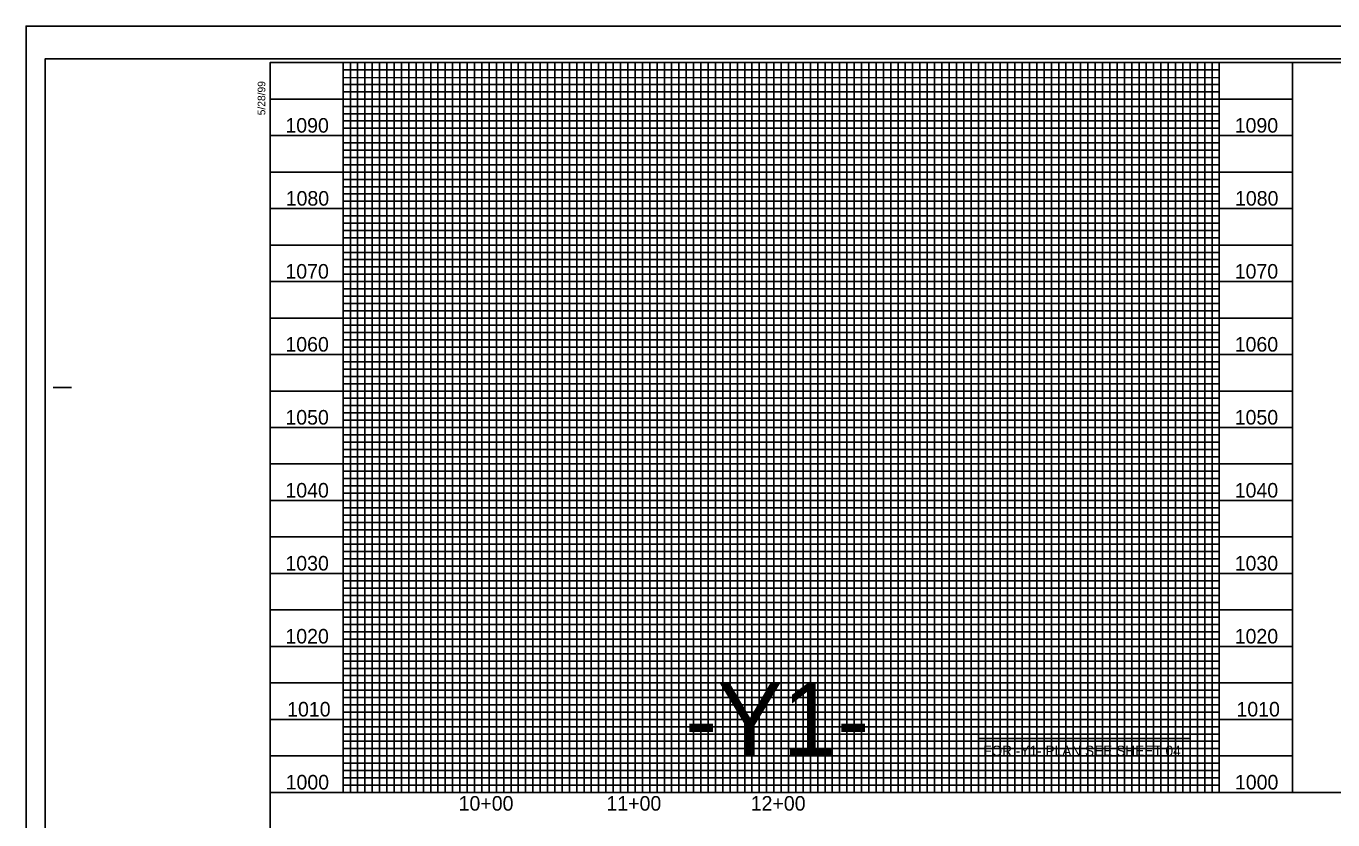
# Model space of a CAD drawing. Extents: x 1260439 to 1262228, y 742196 to 743296.
# Drawn here: x 1260439 to 1261333, y 742752 to 743296 of the extents above; entities that cross this region are included whole.
import ezdxf

# ---------------------------------------------------------------- set-up
doc = ezdxf.new("R2010")
doc.units = 0
for name, color, linetype in [('Exist Vertical Profile Horizontal Axis Label Major', 7, 'Continuous'), ('Exist Vertical Profile Vertical Axis Label', 7, 'Continuous'), ('Prop Grid Mask', 7, 'Continuous'), ('Prop PFL Text', 7, 'Continuous'), ('Scratch_Level_0', 7, 'Continuous'), ('Sheet Cutting Line CELL', 7, 'Continuous'), ('Sheet Data Field CELL', 7, 'Continuous'), ('Sheet Layout Profile Border Port 1', 7, 'Continuous'), ('Sheet Plot Border Inside CELL', 7, 'Continuous'), ('Sheet Plot Border Outside CELL', 7, 'Continuous'), ('Sheet Profile CELL', 7, 'Continuous'), ('Sheet Profile Grid Major CELL', 7, 'Continuous'), ('Sheet Profile Grid Middle CELL', 7, 'Continuous'), ('Sheet Profile Grid Minor CELL', 7, 'Continuous')]:
    doc.layers.add(name, color=color, linetype=linetype)

msp = doc.modelspace()

# ---------------------------------------------------------------- linework, layer by layer
at = {"layer": 'Prop Grid Mask'}
msp.add_lwpolyline([(1261090.75, 742807.74), (1261235.75, 742807.74), (1261235.75, 742790.74), (1261090.75, 742790.74)], close=True, dxfattribs=at)
at = {"layer": 'Scratch_Level_0'}
msp.add_lwpolyline([(1260755.75, 743270.74), (1261355.75, 743270.74), (1261355.75, 742770.74), (1260755.75, 742770.74)], close=True, dxfattribs=at)
at = {"layer": 'Sheet Cutting Line CELL'}
for p, q in [((1262122.75, 743295.74), (1260438.75, 743295.74)), ((1260438.75, 743295.74), (1260438.75, 742195.74))]:
    msp.add_line(p, q, dxfattribs=at)
at = {"layer": 'Sheet Layout Profile Border Port 1'}
msp.add_lwpolyline([(1260655.75, 742770.74), (1261305.75, 742770.74), (1261305.75, 743270.74), (1260655.75, 743270.74)], close=True, dxfattribs=at)
msp.add_lwpolyline([(1260655.75, 743109.69), (1260655.75, 742770.74), (1262055.75, 742770.74), (1262055.75, 743109.69)], dxfattribs=at)
msp.add_lwpolyline([(1260655.75, 743109.69), (1260655.75, 742770.74), (1262055.75, 742770.74), (1262055.75, 743109.69)], dxfattribs=at)
msp.add_lwpolyline([(1260655.75, 743109.69), (1260655.75, 742770.74), (1262055.75, 742770.74), (1262055.75, 743109.69)], dxfattribs=at)
at = {"layer": 'Sheet Plot Border Inside CELL'}
msp.add_lwpolyline([(1260451.75, 742218.19), (1262118.25, 742218.19), (1262118.25, 743273.29), (1260451.75, 743273.29)], close=True, dxfattribs=at)
at = {"layer": 'Sheet Plot Border Outside CELL'}
msp.add_lwpolyline([(1260438.75, 742195.74), (1262122.75, 742195.74), (1262122.75, 743295.74), (1260438.75, 743295.74)], close=True, dxfattribs=at)
at = {"layer": 'Sheet Profile CELL'}
for p, q in [((1260457.25, 743048.24), (1260469.75, 743048.24)), ((1260605.75, 742770.74), (1262105.75, 742770.74))]:
    msp.add_line(p, q, dxfattribs=at)
msp.add_lwpolyline([(1262105.75, 743270.74), (1260605.75, 743270.74), (1260605.75, 742220.74), (1262105.75, 742220.74)], close=True, dxfattribs=at)
at = {"layer": 'Sheet Profile Grid Major CELL'}
for p, q in [((1260655.75, 743270.74), (1260655.75, 742770.74)), ((1260705.75, 742770.74), (1260705.75, 743270.74)), ((1260705.75, 743270.74), (1260755.75, 743270.74)), ((1260755.75, 743270.74), (1260755.75, 742770.74)), ((1260805.75, 742770.74), (1260805.75, 743270.74)), ((1260805.75, 743270.74), (1260855.75, 743270.74)), ((1260855.75, 743270.74), (1260855.75, 742770.74)), ((1260905.75, 742770.74), (1260905.75, 743270.74)), ((1260905.75, 743270.74), (1260955.75, 743270.74)), ((1260955.75, 743270.74), (1260955.75, 742770.74)), ((1261005.75, 742770.74), (1261005.75, 743270.74)), ((1261005.75, 743270.74), (1261055.75, 743270.74)), ((1261055.75, 743270.74), (1261055.75, 742770.74)), ((1261105.75, 742770.74), (1261105.75, 743270.74)), ((1261105.75, 743270.74), (1261155.75, 743270.74)), ((1261155.75, 743270.74), (1261155.75, 742770.74)), ((1261205.75, 742770.74), (1261205.75, 743270.74)), ((1261255.75, 743270.74), (1261255.75, 742770.74)), ((1261305.75, 742770.74), (1261305.75, 743270.74)), ((1260655.75, 742770.74), (1260705.75, 742770.74)), ((1260755.75, 742770.74), (1260805.75, 742770.74)), ((1260855.75, 742770.74), (1260905.75, 742770.74)), ((1260955.75, 742770.74), (1261005.75, 742770.74)), ((1261055.75, 742770.74), (1261105.75, 742770.74)), ((1261155.75, 742770.74), (1261205.75, 742770.74)), ((1261255.75, 742770.74), (1261305.75, 742770.74))]:
    msp.add_line(p, q, dxfattribs=at)
for points in [[(1260605.75, 743220.74), (1261305.75, 743220.74)], [(1261305.75, 743170.74), (1260605.75, 743170.74), (1260605.75, 743120.74), (1261305.75, 743120.74)], [(1261305.75, 743070.74), (1260605.75, 743070.74), (1260605.75, 743020.74), (1261305.75, 743020.74)], [(1261305.75, 742970.74), (1260605.75, 742970.74), (1260605.75, 742920.74), (1261305.75, 742920.74)], [(1261305.75, 742870.74), (1260605.75, 742870.74), (1260605.75, 742870.74), (1260605.75, 742820.74), (1261305.75, 742820.74)]]:
    msp.add_lwpolyline(points, dxfattribs=at)
at = {"layer": 'Sheet Profile Grid Middle CELL'}
for p, q in [((1260680.75, 743270.74), (1260680.75, 742770.74)), ((1260730.75, 742770.74), (1260730.75, 743270.74)), ((1260730.75, 743270.74), (1260780.75, 743270.74)), ((1260780.75, 743270.74), (1260780.75, 742770.74)), ((1260830.75, 742770.74), (1260830.75, 743270.74)), ((1260830.75, 743270.74), (1260880.75, 743270.74)), ((1260880.75, 743270.74), (1260880.75, 742770.74)), ((1260930.75, 742770.74), (1260930.75, 743270.74)), ((1260930.75, 743270.74), (1260980.75, 743270.74)), ((1260980.75, 743270.74), (1260980.75, 742770.74)), ((1261030.75, 742770.74), (1261030.75, 743270.74)), ((1261030.75, 743270.74), (1261080.75, 743270.74)), ((1261080.75, 743270.74), (1261080.75, 742770.74)), ((1261130.75, 742770.74), (1261130.75, 743270.74)), ((1261180.75, 743270.74), (1261180.75, 742770.74)), ((1261230.75, 742770.74), (1261230.75, 743270.74)), ((1260605.75, 743245.74), (1261305.75, 743245.74)), ((1260680.75, 742770.74), (1260730.75, 742770.74)), ((1260780.75, 742770.74), (1260830.75, 742770.74)), ((1260880.75, 742770.74), (1260930.75, 742770.74)), ((1260980.75, 742770.74), (1261030.75, 742770.74)), ((1261080.75, 742770.74), (1261130.75, 742770.74)), ((1261230.75, 742770.74), (1261230.75, 742770.74))]:
    msp.add_line(p, q, dxfattribs=at)
for points in [[(1261305.75, 743195.74), (1260605.75, 743195.74), (1260605.75, 743145.74), (1261305.75, 743145.74)], [(1261305.75, 743095.74), (1260605.75, 743095.74), (1260605.75, 743045.74), (1261305.75, 743045.74)], [(1261305.75, 742995.74), (1260605.75, 742995.74), (1260605.75, 742945.74), (1261305.75, 742945.74)], [(1261305.75, 742895.74), (1260605.75, 742895.74), (1260605.75, 742845.74), (1261305.75, 742845.74)], [(1261305.75, 742795.74), (1260605.75, 742795.74)]]:
    msp.add_lwpolyline(points, dxfattribs=at)
at = {"layer": 'Sheet Profile Grid Minor CELL'}
for p, q in [((1260655.75, 743265.74), (1261255.75, 743265.74)), ((1260655.75, 743260.74), (1260655.75, 743260.74)), ((1261255.75, 743260.56), (1260655.75, 743260.39)), ((1260655.75, 743255.74), (1261255.75, 743255.74)), ((1261255.75, 743135.74), (1260655.75, 743135.74)), ((1261255.75, 743130.74), (1260655.75, 743130.74)), ((1261255.75, 743125.74), (1260655.75, 743125.74)), ((1260655.75, 743115.74), (1261255.75, 743115.74)), ((1261255.75, 743110.74), (1260655.75, 743110.74)), ((1260655.75, 743105.74), (1261255.75, 743105.74)), ((1261255.75, 743085.74), (1260655.75, 743085.74)), ((1260655.75, 743080.74), (1261255.75, 743080.74)), ((1261255.75, 743060.74), (1260655.75, 743060.74)), ((1260655.75, 743055.74), (1261255.75, 743055.74)), ((1261255.75, 743035.74), (1260655.75, 743035.74)), ((1260655.75, 743030.74), (1261255.75, 743030.74)), ((1261255.75, 743025.74), (1260655.75, 743025.74)), ((1260655.75, 743015.74), (1261255.75, 743015.74)), ((1261255.75, 743010.74), (1260655.75, 743010.74)), ((1260655.75, 743005.74), (1261255.75, 743005.74)), ((1261255.75, 743000.74), (1260655.75, 743000.74)), ((1260655.75, 742990.74), (1261255.75, 742990.74)), ((1261255.75, 742985.74), (1260655.75, 742985.74)), ((1260655.75, 742980.74), (1261255.75, 742980.74)), ((1261255.75, 742975.74), (1260655.75, 742975.74)), ((1260655.75, 742965.74), (1261255.75, 742965.74)), ((1261255.75, 742960.74), (1260655.75, 742960.74)), ((1260655.75, 742955.74), (1261255.75, 742955.74)), ((1261255.75, 742950.74), (1260655.75, 742950.74)), ((1260655.75, 742940.74), (1261255.75, 742940.74)), ((1261255.75, 742935.74), (1260655.75, 742935.74)), ((1260655.75, 742930.74), (1261255.75, 742930.74)), ((1261255.75, 742925.74), (1260655.75, 742925.74)), ((1260655.75, 742915.74), (1261255.75, 742915.74)), ((1261255.75, 742910.74), (1260655.75, 742910.74)), ((1260655.75, 742905.74), (1261255.75, 742905.74)), ((1261255.75, 742900.74), (1260655.75, 742900.74)), ((1260655.75, 742890.74), (1261255.75, 742890.74)), ((1261255.75, 742885.74), (1260655.75, 742885.74)), ((1261255.75, 742880.74), (1260655.75, 742880.74)), ((1261255.75, 742875.74), (1260655.75, 742875.74)), ((1260655.75, 742865.74), (1261255.75, 742865.74)), ((1261255.75, 742860.74), (1260655.75, 742860.74)), ((1260655.75, 742855.74), (1261255.75, 742855.74)), ((1261255.75, 742850.74), (1260655.75, 742850.74)), ((1260655.75, 742840.74), (1261255.75, 742840.74)), ((1261255.75, 742835.74), (1260655.75, 742835.74)), ((1260655.75, 742830.74), (1261255.75, 742830.74)), ((1261255.75, 742825.74), (1260655.75, 742825.74)), ((1260655.75, 742815.74), (1261255.75, 742815.74)), ((1261255.75, 742810.74), (1260655.75, 742810.74)), ((1260655.75, 742805.74), (1261255.75, 742805.74)), ((1261255.75, 742800.74), (1260655.75, 742800.74)), ((1260655.75, 742790.74), (1261255.75, 742790.74)), ((1261255.75, 742785.74), (1260655.75, 742785.74)), ((1260655.75, 742780.74), (1261255.75, 742780.74))]:
    msp.add_line(p, q, dxfattribs=at)
for points in [[(1260660.75, 743270.74), (1260660.75, 742770.74), (1260665.75, 742770.74), (1260665.75, 743270.74), (1260670.75, 743270.74), (1260670.75, 742770.74), (1260675.75, 742770.74), (1260675.75, 743270.74), (1260685.75, 743270.74), (1260685.75, 742770.74), (1260690.75, 742770.74), (1260690.75, 743270.74), (1260695.75, 743270.74), (1260695.75, 742770.74), (1260700.75, 742770.74), (1260710.75, 742770.74), (1260715.75, 742770.74), (1260715.75, 743270.74), (1260720.75, 743270.74), (1260720.75, 742770.74), (1260725.75, 742770.74), (1260725.75, 743270.74), (1260735.75, 743270.74), (1260735.75, 742770.74), (1260740.75, 742770.74), (1260740.75, 743270.74), (1260745.75, 743270.74), (1260745.75, 742770.74), (1260750.75, 742770.74), (1260750.75, 743270.74), (1260760.75, 743270.74), (1260760.75, 742770.74), (1260765.75, 742770.74), (1260765.75, 743270.74), (1260770.75, 743270.74), (1260770.75, 742770.74), (1260775.75, 742770.74), (1260775.75, 743270.74), (1260785.75, 743270.74), (1260785.75, 742770.74), (1260790.75, 742770.74), (1260790.75, 743270.74), (1260795.75, 743270.74), (1260795.75, 742770.74), (1260800.75, 742770.74), (1260800.75, 743270.74), (1260810.75, 743270.74), (1260810.75, 742770.74), (1260815.75, 742770.74), (1260815.75, 743270.74), (1260820.75, 743270.74), (1260820.75, 742770.74), (1260825.75, 742770.74), (1260825.75, 743270.74), (1260835.75, 743270.74), (1260835.75, 742770.74), (1260840.75, 742770.74), (1260840.75, 743270.74), (1260845.75, 743270.74), (1260845.75, 742770.74), (1260850.75, 742770.74), (1260850.75, 743270.74), (1260860.75, 743270.74), (1260860.75, 742770.74), (1260865.75, 742770.74), (1260865.75, 743270.74), (1260870.75, 743270.74), (1260870.75, 742770.74)], [(1260700.75, 742770.74), (1260700.75, 743270.74), (1260710.75, 743270.74), (1260710.75, 742770.74)], [(1260870.75, 742770.74), (1260875.75, 742770.74), (1260875.75, 743270.74), (1260885.75, 743270.74), (1260885.75, 742770.74), (1260890.75, 742770.74), (1260890.75, 743270.74), (1260895.75, 743270.74), (1260895.75, 742770.74), (1260900.75, 742770.74), (1260900.75, 743270.74), (1260910.75, 743270.74), (1260910.75, 742770.74), (1260915.75, 742770.74), (1260915.75, 743270.74), (1260920.75, 743270.74), (1260920.75, 742770.74), (1260925.75, 742770.74), (1260925.75, 743270.74), (1260935.75, 743270.74), (1260935.75, 742770.74), (1260940.75, 742770.74), (1260940.75, 743270.74), (1260945.75, 743270.74), (1260945.75, 742770.74), (1260950.75, 742770.74), (1260950.75, 743270.74), (1260960.75, 743270.74), (1260960.75, 742770.74), (1260965.75, 742770.74), (1260965.75, 743270.74), (1260970.75, 743270.74), (1260970.75, 742770.74), (1260975.75, 742770.74), (1260975.75, 743270.74), (1260985.75, 743270.74), (1260985.75, 742770.74), (1260990.75, 742770.74), (1260990.75, 743270.74), (1260995.75, 743270.74), (1260995.75, 742770.74), (1261000.75, 742770.74), (1261000.75, 743270.74), (1261010.75, 743270.74), (1261010.75, 742770.74), (1261015.75, 742770.74), (1261015.75, 743270.74), (1261020.75, 743270.74), (1261020.75, 742770.74), (1261025.75, 742770.74), (1261025.75, 743270.74), (1261035.75, 743270.74), (1261035.75, 742770.74), (1261040.75, 742770.74), (1261040.75, 743270.74), (1261045.75, 743270.74), (1261045.75, 742770.74), (1261050.75, 742770.74), (1261050.75, 743270.74), (1261060.75, 743270.74), (1261060.75, 742770.74), (1261065.75, 742770.74), (1261065.75, 743270.74), (1261070.75, 743270.74), (1261070.75, 742770.74), (1261075.75, 742770.74), (1261075.75, 743270.74), (1261085.75, 743270.74), (1261085.75, 742770.74), (1261090.75, 742770.74), (1261090.75, 743270.74), (1261095.75, 743270.74), (1261095.75, 742770.74), (1261100.75, 742770.74), (1261100.75, 743270.74), (1261110.75, 743270.74), (1261110.75, 742770.74), (1261115.75, 742770.74), (1261115.75, 743270.74), (1261120.75, 743270.74), (1261120.75, 742770.74), (1261125.75, 742770.74), (1261125.75, 743270.74), (1261135.75, 743270.74), (1261135.75, 742770.74), (1261140.75, 742770.74), (1261140.75, 743270.74), (1261145.75, 743270.74), (1261145.75, 742770.74), (1261150.75, 742770.74), (1261150.75, 743270.74), (1261255.75, 743270.74)], [(1261145.75, 742770.74), (1261150.75, 742770.74), (1261150.75, 743270.74), (1261160.75, 743270.74), (1261160.75, 742770.74), (1261165.75, 742770.74), (1261165.75, 743270.74), (1261170.75, 743270.74), (1261170.75, 742770.74), (1261175.75, 742770.74), (1261175.75, 743270.74), (1261185.75, 743270.74), (1261185.75, 742770.74), (1261190.75, 742770.74), (1261190.75, 743270.74), (1261195.75, 743270.74), (1261195.75, 742770.74), (1261200.75, 742770.74), (1261200.75, 743270.74), (1261210.75, 743270.74), (1261210.75, 742770.74), (1261215.75, 742770.74), (1261215.75, 743270.74), (1261220.75, 743270.74), (1261220.75, 742770.74), (1261225.75, 742770.74), (1261225.75, 743270.74), (1261235.75, 743270.74), (1261235.75, 742770.74), (1261240.75, 742770.74), (1261240.75, 743270.74), (1261245.75, 743270.74), (1261245.75, 742770.74), (1261250.75, 742770.74), (1261250.75, 743270.74), (1261255.75, 743270.74)], [(1261255.75, 743250.74), (1260655.75, 743250.74), (1260655.75, 743240.74), (1261255.75, 743240.74)], [(1261255.75, 743235.74), (1260655.75, 743235.74), (1260655.75, 743230.74), (1261255.75, 743230.74)], [(1261255.75, 743225.74), (1260655.75, 743225.74), (1260655.75, 743215.74), (1261255.75, 743215.74)], [(1261255.75, 743210.74), (1260655.75, 743210.74), (1260655.75, 743205.74), (1261255.75, 743205.74)], [(1261255.75, 743200.74), (1260655.75, 743200.74), (1260655.75, 743190.74), (1261255.75, 743190.74)], [(1261255.75, 743185.74), (1260655.75, 743185.74), (1260655.75, 743180.74), (1261255.75, 743180.74)], [(1261255.75, 743175.74), (1260655.75, 743175.74), (1260655.75, 743165.74), (1261255.75, 743165.74)], [(1261255.75, 743160.64), (1260655.85, 743160.64), (1260655.85, 743155.74), (1261255.75, 743155.74)], [(1261255.75, 743150.74), (1260655.75, 743150.74), (1260655.75, 743140.74), (1261255.75, 743140.74)], [(1261255.75, 743100.74), (1260655.75, 743100.74), (1260655.75, 743090.74), (1261255.75, 743090.74)], [(1261255.75, 743075.74), (1260655.75, 743075.74), (1260655.75, 743065.74), (1261255.75, 743065.74)], [(1261255.75, 743050.74), (1260655.75, 743050.74), (1260655.75, 743040.74), (1261255.75, 743040.74)], [(1261255.75, 742775.74), (1260655.75, 742775.74)]]:
    msp.add_lwpolyline(points, dxfattribs=at)

# ---------------------------------------------------------------- texts
at = {"layer": 'Exist Vertical Profile Horizontal Axis Label Major'}
for s, p in [('10+00', (1260734.88, 742758.24)), ('11+00', (1260836.08, 742758.24)), ('12+00', (1260934.88, 742758.24))]:
    msp.add_text(s, height=10, dxfattribs=at).set_placement(p)
at = {"layer": 'Exist Vertical Profile Vertical Axis Label'}
for s, p in [('1090', (1260616.27, 743222.74)), ('1090', (1261266.27, 743222.74)), ('1080', (1260616.47, 743172.74)), ('1080', (1261266.47, 743172.74)), ('1070', (1260616.27, 743122.74)), ('1070', (1261266.27, 743122.74)), ('1060', (1260616.27, 743072.74)), ('1060', (1261266.27, 743072.74)), ('1050', (1260616.27, 743022.74)), ('1050', (1261266.27, 743022.74)), ('1040', (1260616.27, 742972.74)), ('1040', (1261266.27, 742972.74)), ('1030', (1260616.27, 742922.74)), ('1030', (1261266.27, 742922.74)), ('1020', (1260616.27, 742872.74)), ('1020', (1261266.27, 742872.74)), ('1010', (1260617.47, 742822.74)), ('1010', (1261267.47, 742822.74)), ('1000', (1260616.43, 742772.74)), ('1000', (1261266.43, 742772.74))]:
    msp.add_text(s, height=10, dxfattribs=at).set_placement(p)
at = {"layer": 'Prop PFL Text'}
msp.add_text('FOR -Y1- PLAN SEE SHEET 04', height=7, dxfattribs=at).set_placement((1261094.08, 742795.74))
at = {"layer": 'Sheet Data Field CELL'}
msp.add_text('-Y1-', height=50, dxfattribs=at).set_placement((1260889.85, 742795.74))
at = {"layer": 'Sheet Profile CELL'}
msp.add_text('5/28/99', height=5.25, rotation=90, dxfattribs=at).set_placement((1260602.52, 743234.65))

doc.saveas('drawing.dxf')
